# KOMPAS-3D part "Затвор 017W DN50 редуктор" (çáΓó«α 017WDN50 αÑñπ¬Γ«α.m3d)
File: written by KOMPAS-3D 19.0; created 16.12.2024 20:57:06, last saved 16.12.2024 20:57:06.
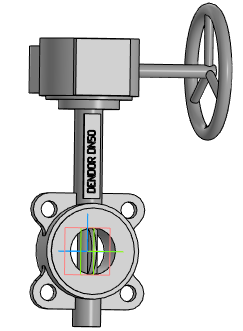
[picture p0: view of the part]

Document properties: Автор: Евгений; Полное имя файла: ..\Затвор 017WDN50 редуктор.a3d

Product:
- Part/product: Затвор 017W DN50 редуктор
    Масса: 9.85787

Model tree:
1. Операция без истории:1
